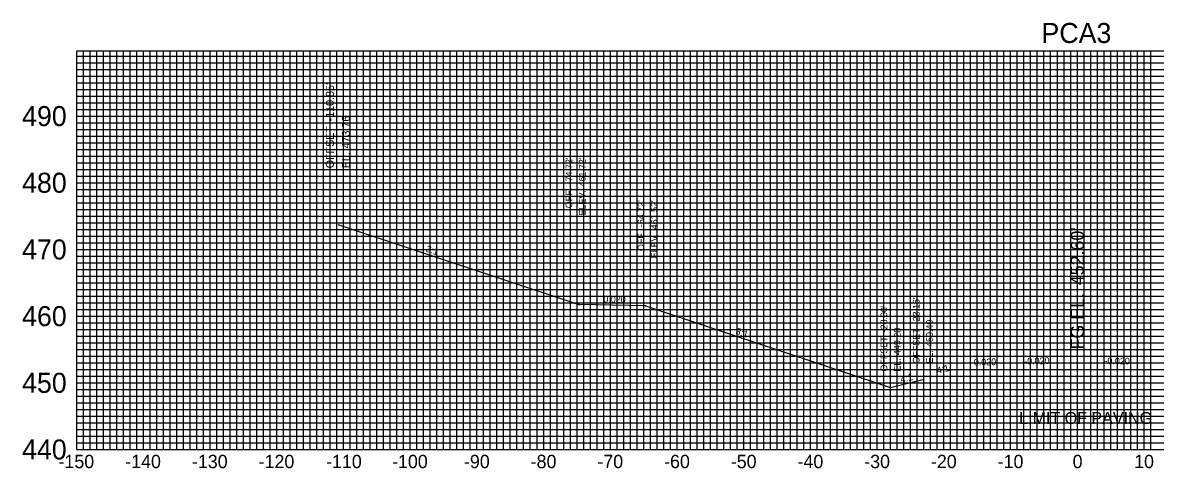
# Model space of a CAD drawing. Extents: x -158 to 158, y 433 to 504.
# Drawn here: x -158.1 to 11.7, y 437.2 to 504 of the extents above; entities that cross this region are included whole.
import ezdxf

# ---------------------------------------------------------------- set-up
doc = ezdxf.new("R2010")
doc.units = 0
for name, color, linetype in [('_CIVIL_CONSTRUCTION', 7, 'Continuous'), ('Default', 7, 'Continuous'), ('DES - MODEL - CPNT - Grass', 7, 'Continuous'), ('DES - SHEET - Light Grid', 7, 'Continuous'), ('DES - SHEET - Linework', 7, 'Continuous'), ('DES - XS - Proposed - Finished Grade Slopes Text', 7, 'Continuous'), ('DES - XS - Proposed - Text', 7, 'Continuous'), ('Draft_XS_Volume_Annotation', 7, 'Continuous')]:
    doc.layers.add(name, color=color, linetype=linetype)

msp = doc.modelspace()

# ---------------------------------------------------------------- linework, layer by layer
at = {"layer": '_CIVIL_CONSTRUCTION'}
for centre in [(-74.72, 461.72), (-64.72, 461.52)]:
    msp.add_circle(centre, 0.05, dxfattribs=at)
at = {"layer": 'Default'}
msp.add_circle((0, 448.4), 0.012, dxfattribs=at)
msp.add_circle((0, 448.4), 0.012, dxfattribs=at)
msp.add_circle((0, 448.4), 0.012, dxfattribs=at)
at = {"layer": 'DES - MODEL - CPNT - Grass'}
for p, q in [((-110.85, 473.76), (-74.72, 461.72)), ((-64.72, 461.52), (-74.72, 461.72)), ((-64.72, 461.52), (-28, 449.28)), ((-28, 449.28), (-23.16, 450.49))]:
    msp.add_line(p, q, dxfattribs=at)
at = {"layer": 'DES - SHEET - Light Grid'}
for p, q in [((-149, 440), (-149, 499.76)), ((-148, 440), (-148, 499.76)), ((-147, 440), (-147, 499.76)), ((-146, 440), (-146, 499.76)), ((-145, 440), (-145, 499.76)), ((-144, 440), (-144, 499.76)), ((-143, 440), (-143, 499.76)), ((-142, 440), (-142, 499.76)), ((-141, 440), (-141, 499.76)), ((-139, 440), (-139, 499.76)), ((-138, 440), (-138, 499.76)), ((-137, 440), (-137, 499.76)), ((-136, 440), (-136, 499.76)), ((-135, 440), (-135, 499.76)), ((-134, 440), (-134, 499.76)), ((-133, 440), (-133, 499.76)), ((-132, 440), (-132, 499.76)), ((-131, 440), (-131, 499.76)), ((-129, 440), (-129, 499.76)), ((-128, 440), (-128, 499.76)), ((-127, 440), (-127, 499.76)), ((-126, 440), (-126, 499.76)), ((-125, 440), (-125, 499.76)), ((-124, 440), (-124, 499.76)), ((-123, 440), (-123, 499.76)), ((-122, 440), (-122, 499.76)), ((-121, 440), (-121, 499.76)), ((-119, 440), (-119, 499.76)), ((-118, 440), (-118, 499.76)), ((-117, 440), (-117, 499.76)), ((-116, 440), (-116, 499.76)), ((-115, 440), (-115, 499.76)), ((-114, 440), (-114, 499.76)), ((-113, 440), (-113, 499.76)), ((-112, 440), (-112, 499.76)), ((-111, 440), (-111, 499.76)), ((-109, 440), (-109, 499.76)), ((-108, 440), (-108, 499.76)), ((-107, 440), (-107, 499.76)), ((-106, 440), (-106, 499.76)), ((-105, 440), (-105, 499.76)), ((-104, 440), (-104, 499.76)), ((-103, 440), (-103, 499.76)), ((-102, 440), (-102, 499.76)), ((-101, 440), (-101, 499.76)), ((-99, 440), (-99, 499.76)), ((-98, 440), (-98, 499.76)), ((-97, 440), (-97, 499.76)), ((-96, 440), (-96, 499.76)), ((-95, 440), (-95, 499.76)), ((-94, 440), (-94, 499.76)), ((-93, 440), (-93, 499.76)), ((-92, 440), (-92, 499.76)), ((-91, 440), (-91, 499.76)), ((-89, 440), (-89, 499.76)), ((-88, 440), (-88, 499.76)), ((-87, 440), (-87, 499.76)), ((-86, 440), (-86, 499.76)), ((-85, 440), (-85, 499.76)), ((-84, 440), (-84, 499.76)), ((-83, 440), (-83, 499.76)), ((-82, 440), (-82, 499.76)), ((-81, 440), (-81, 499.76)), ((-79, 440), (-79, 499.76)), ((-78, 440), (-78, 499.76)), ((-77, 440), (-77, 499.76)), ((-76, 440), (-76, 499.76)), ((-75, 440), (-75, 499.76)), ((-74, 440), (-74, 499.76)), ((-73, 440), (-73, 499.76)), ((-72, 440), (-72, 499.76)), ((-71, 440), (-71, 499.76)), ((-69, 440), (-69, 499.76)), ((-68, 440), (-68, 499.76)), ((-67, 440), (-67, 499.76)), ((-66, 440), (-66, 499.76)), ((-65, 440), (-65, 499.76)), ((-64, 440), (-64, 499.76)), ((-63, 440), (-63, 499.76)), ((-62, 440), (-62, 499.76)), ((-61, 440), (-61, 499.76)), ((-59, 440), (-59, 499.76)), ((-58, 440), (-58, 499.76)), ((-57, 440), (-57, 499.76)), ((-56, 440), (-56, 499.76)), ((-55, 440), (-55, 499.76)), ((-54, 440), (-54, 499.76)), ((-53, 440), (-53, 499.76)), ((-52, 440), (-52, 499.76)), ((-51, 440), (-51, 499.76)), ((-49, 440), (-49, 499.76)), ((-48, 440), (-48, 499.76)), ((-47, 440), (-47, 499.76)), ((-46, 440), (-46, 499.76)), ((-45, 440), (-45, 499.76)), ((-44, 440), (-44, 499.76)), ((-43, 440), (-43, 499.76)), ((-42, 440), (-42, 499.76)), ((-41, 440), (-41, 499.76)), ((-39, 440), (-39, 499.76)), ((-38, 440), (-38, 499.76)), ((-37, 440), (-37, 499.76)), ((-36, 440), (-36, 499.76)), ((-35, 440), (-35, 499.76)), ((-34, 440), (-34, 499.76)), ((-33, 440), (-33, 499.76)), ((-32, 440), (-32, 499.76)), ((-31, 440), (-31, 499.76)), ((-29, 440), (-29, 499.76)), ((-28, 440), (-28, 499.76)), ((-27, 440), (-27, 499.76)), ((-26, 440), (-26, 499.76)), ((-25, 440), (-25, 499.76)), ((-24, 440), (-24, 499.76)), ((-23, 440), (-23, 499.76)), ((-22, 440), (-22, 499.76)), ((-21, 440), (-21, 499.76)), ((-19, 440), (-19, 499.76)), ((-18, 440), (-18, 499.76)), ((-17, 440), (-17, 499.76)), ((-16, 440), (-16, 499.76)), ((-15, 440), (-15, 499.76)), ((-14, 440), (-14, 499.76)), ((-13, 440), (-13, 499.76)), ((-12, 440), (-12, 499.76)), ((-11, 440), (-11, 499.76)), ((-9, 440), (-9, 499.76)), ((-8, 440), (-8, 499.76)), ((-7, 440), (-7, 499.76)), ((-6, 440), (-6, 499.76)), ((-5, 440), (-5, 499.76)), ((-4, 440), (-4, 499.76)), ((-3, 440), (-3, 499.76)), ((-2, 440), (-2, 499.76)), ((-1, 440), (-1, 499.76)), ((1, 440), (1, 499.76)), ((2, 440), (2, 499.76)), ((3, 440), (3, 499.76)), ((4, 440), (4, 499.76)), ((5, 440), (5, 499.76)), ((6, 440), (6, 499.76)), ((7, 440), (7, 499.76)), ((8, 440), (8, 499.76)), ((9, 440), (9, 499.76)), ((11, 440), (11, 499.76)), ((-150, 499), (150, 499)), ((-150, 498), (150, 498)), ((-150, 497), (150, 497)), ((-150, 496), (150, 496)), ((-150, 495), (150, 495)), ((-150, 494), (150, 494)), ((-150, 493), (150, 493)), ((-150, 492), (150, 492)), ((-150, 491), (150, 491)), ((-150, 489), (150, 489)), ((-150, 488), (150, 488)), ((-150, 487), (150, 487)), ((-150, 486), (150, 486)), ((-150, 485), (150, 485)), ((-150, 484), (150, 484)), ((-150, 483), (150, 483)), ((-150, 482), (150, 482)), ((-150, 481), (150, 481)), ((-150, 479), (150, 479)), ((-150, 478), (150, 478)), ((-150, 477), (150, 477)), ((-150, 476), (150, 476)), ((-150, 475), (150, 475)), ((-150, 474), (150, 474)), ((-150, 473), (150, 473)), ((-150, 472), (150, 472)), ((-150, 471), (150, 471)), ((-150, 469), (150, 469)), ((-150, 468), (150, 468)), ((-150, 467), (150, 467)), ((-150, 466), (150, 466)), ((-150, 465), (150, 465)), ((-150, 464), (150, 464)), ((-150, 463), (150, 463)), ((-150, 462), (150, 462)), ((-150, 461), (150, 461)), ((-150, 459), (150, 459)), ((-150, 458), (150, 458)), ((-150, 457), (150, 457)), ((-150, 456), (150, 456)), ((-150, 455), (150, 455)), ((-150, 454), (150, 454)), ((-150, 453), (150, 453)), ((-150, 452), (150, 452)), ((-150, 451), (150, 451)), ((-150, 449), (150, 449)), ((-150, 448), (150, 448)), ((-150, 447), (150, 447)), ((-150, 446), (150, 446)), ((-150, 445), (150, 445)), ((-150, 444), (150, 444)), ((-150, 443), (150, 443)), ((-150, 442), (150, 442)), ((-150, 441), (150, 441))]:
    msp.add_line(p, q, dxfattribs=at)
at = {"layer": 'DES - SHEET - Linework'}
for p, q in [((-150, 499.76), (150, 499.76)), ((-150, 440), (-150, 499.76)), ((-140, 440), (-140, 499.76)), ((-130, 440), (-130, 499.76)), ((-120, 440), (-120, 499.76)), ((-110, 440), (-110, 499.76)), ((-100, 440), (-100, 499.76)), ((-90, 440), (-90, 499.76)), ((-80, 440), (-80, 499.76)), ((-70, 440), (-70, 499.76)), ((-60, 440), (-60, 499.76)), ((-50, 440), (-50, 499.76)), ((-40, 440), (-40, 499.76)), ((-30, 440), (-30, 499.76)), ((-20, 440), (-20, 499.76)), ((-10, 440), (-10, 499.76)), ((0, 440), (0, 499.76)), ((10, 440), (10, 499.76)), ((-150, 490), (150, 490)), ((-150, 480), (150, 480)), ((-150, 470), (150, 470)), ((-150, 460), (150, 460)), ((-150, 450), (150, 450)), ((-150, 440), (150, 440))]:
    msp.add_line(p, q, dxfattribs=at)
at = {"layer": 'Draft_XS_Volume_Annotation'}
msp.add_circle((0, 448.4), 0.012, dxfattribs=at)
msp.add_circle((0, 448.4), 0.012, dxfattribs=at)
msp.add_circle((0, 448.4), 0.012, dxfattribs=at)
msp.add_circle((0, 448.4), 0.012, dxfattribs=at)
msp.add_circle((0, 448.4), 0.012, dxfattribs=at)
msp.add_circle((0, 448.4), 0.012, dxfattribs=at)

# ---------------------------------------------------------------- texts
at = {"layer": 'DES - XS - Proposed - Finished Grade Slopes Text'}
for s, height, rotation, p in [("-110.85'", 1.2, 90, (-111.45, 489.21)), ('473.76', 1.2, 90, (-109.05, 485.14)), ('OFFSET ', 1.2, 90, (-111.45, 482.16)), ('EL. ', 1.2, 90, (-109.05, 482.16)), ('3:1', 1, 341.5668, (-97.73, 469.69)), ('0.020', 1, 358.8542, (-71.06, 462.05)), ('3:1', 1, 341.5668, (-51.3, 457.35)), ('-0.020', 1, 1.1458, (-15.95, 452.58)), ('-0.020', 1, 1.1458, (-7.95, 452.74)), ('-0.020', 1, 358.8542, (4.05, 452.82)), ('4:1', 1, 14.0362, (-20.94, 451.35)), ('4:1', 1, 14.0362, (-26.39, 449.98))]:
    msp.add_text(s, height=height, rotation=rotation, dxfattribs=at).set_placement(p)
msp.add_text('LIMIT OF PAVING', height=1.8, dxfattribs=at).set_placement((-8.72, 443.82))
at = {"layer": 'DES - XS - Proposed - Text'}
for s, height, p in [('PCA3', 3, (-5.38, 500.96)), ('490', 3, (-158.19, 488.5)), ('480', 3, (-158.19, 478.5)), ('470', 3, (-158.19, 468.5)), ('460', 3, (-158.19, 458.5)), ('450', 3, (-158.19, 448.5)), ('440', 3, (-158.19, 438.5)), ('-150', 2, (-152.73, 437.2)), ('-140', 2, (-142.73, 437.2)), ('-130', 2, (-132.73, 437.2)), ('-120', 2, (-122.73, 437.2)), ('-110', 2, (-112.62, 437.2)), ('-100', 2, (-102.73, 437.2)), ('-90', 2, (-91.95, 437.2)), ('-80', 2, (-81.95, 437.2)), ('-70', 2, (-71.95, 437.2)), ('-60', 2, (-61.95, 437.2)), ('-50', 2, (-51.95, 437.2)), ('-40', 2, (-41.95, 437.2)), ('-30', 2, (-31.95, 437.2)), ('-20', 2, (-21.95, 437.2)), ('-10', 2, (-11.95, 437.2)), ('0', 2, (-0.71, 437.2)), ('10', 2, (8.51, 437.2))]:
    msp.add_text(s, height=height, dxfattribs=at).set_placement(p)
for s, height, p in [("-74.72'", 1, (-75.72, 479.75)), ("461.72'", 1, (-73.72, 479.44)), ('OFF. ', 1, (-75.72, 476.18)), ('ELEV. ', 1, (-73.72, 475.09)), ("-64.72'", 1, (-64.92, 473.33)), ("461.52'", 1, (-62.92, 473.02)), ('OFF. ', 1, (-64.92, 469.76)), ('ELEV. ', 1, (-62.92, 468.67)), ("452.60'", 2, (1, 464.63)), ("-23.16'", 1, (-23.66, 458.77)), ('FG EL. ', 2, (1, 455)), ("-28.00'", 1, (-28.5, 457.56)), ('450.49', 1, (-21.66, 455.38)), ('OFFSET ', 1, (-28.5, 451.68)), ('449.28', 1, (-26.5, 454.16)), ('OFFSET ', 1, (-23.66, 452.89)), ('EL. ', 1, (-26.5, 451.68)), ('EL. ', 1, (-21.66, 452.89))]:
    msp.add_text(s, height=height, rotation=90, dxfattribs=at).set_placement(p)

doc.saveas('drawing.dxf')
